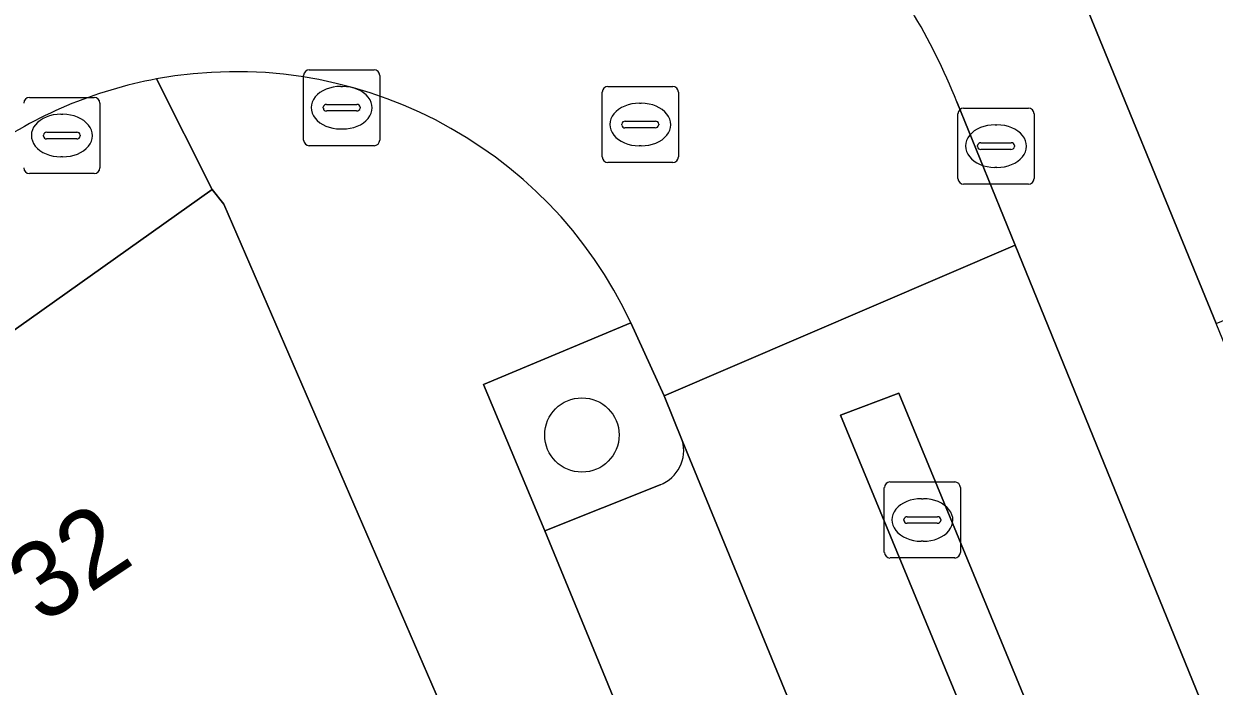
# Model space of a CAD drawing. Extents: x 161771 to 163125, y 382475 to 383179.
# Drawn here: x 161911.65 to 161927.3, y 383066.21 to 383074.92 of the extents above; entities that cross this region are included whole.
import ezdxf

# ---------------------------------------------------------------- set-up
doc = ezdxf.new("R2010")
doc.units = 0
for name, color, linetype in [('IMGEO_Boom', 7, 'Continuous'), ('IMGEO_Groenvoorziening', 7, 'Continuous'), ('IMGEO_Kolk', 7, 'Continuous'), ('IMGEO_Pand', 7, 'Continuous'), ('IMGEO_Pand_nummerreeks', 7, 'Continuous'), ('IMGEO_Parkeervlak_open', 7, 'Continuous'), ('IMGEO_Rijbaan_lokaal_open', 7, 'Continuous'), ('IMGEO_Rioolput', 7, 'Continuous'), ('IMGEO_Voetpad_open', 7, 'Continuous')]:
    doc.layers.add(name, color=color, linetype=linetype)

msp = doc.modelspace()

# ---------------------------------------------------------------- linework, layer by layer
at = {"layer": 'IMGEO_Boom'}
msp.add_circle((161918.987, 383069.512), 0.489, dxfattribs=at)
at = {"layer": 'IMGEO_Groenvoorziening'}
for points in [[(161920.07, 383070.029), (161919.632, 383070.986), (161917.694, 383070.178), (161918.501, 383068.252), (161920.014, 383068.858)], [(161920.306, 383069.44), (161920.07, 383070.029)]]:
    msp.add_lwpolyline(points, dxfattribs=at)
msp.add_arc((161919.843, 383069.308), 0.482, 290.8495, 15.8629, dxfattribs=at)
at = {"layer": 'IMGEO_Kolk'}
for p, q in [((161915.328, 383073.391), (161915.328, 383074.243)), ((161915.403, 383074.317), (161916.255, 383074.317)), ((161916.329, 383074.243), (161916.329, 383073.391)), ((161915.816, 383074.097), (161915.841, 383074.097)), ((161911.724, 383073.951), (161912.576, 383073.951)), ((161912.137, 383073.731), (161912.162, 383073.731)), ((161912.65, 383073.877), (161912.65, 383073.025)), ((161915.587, 383073.811), (161915.587, 383073.823)), ((161916.025, 383073.774), (161915.627, 383073.774)), ((161915.63, 383073.86), (161916.028, 383073.86)), ((161916.071, 383073.823), (161916.071, 383073.811)), ((161923.93, 383072.886), (161923.93, 383073.738)), ((161924.005, 383073.812), (161924.857, 383073.812)), ((161924.931, 383073.738), (161924.931, 383072.886)), ((161924.418, 383073.592), (161924.443, 383073.592)), ((161911.908, 383073.445), (161911.908, 383073.457)), ((161911.951, 383073.494), (161912.349, 383073.494)), ((161912.392, 383073.457), (161912.392, 383073.445)), ((161915.839, 383073.537), (161915.814, 383073.537)), ((161912.346, 383073.408), (161911.948, 383073.408)), ((161916.255, 383073.317), (161915.403, 383073.317)), ((161924.189, 383073.306), (161924.189, 383073.318)), ((161924.627, 383073.269), (161924.229, 383073.269)), ((161924.232, 383073.355), (161924.63, 383073.355)), ((161924.673, 383073.318), (161924.673, 383073.306)), ((161912.16, 383073.171), (161912.135, 383073.171)), ((161912.576, 383072.951), (161911.724, 383072.951)), ((161924.441, 383073.032), (161924.416, 383073.032)), ((161924.857, 383072.812), (161924.005, 383072.812)), ((161923.037, 383068.894), (161923.889, 383068.894)), ((161922.962, 383067.968), (161922.962, 383068.82)), ((161923.963, 383068.82), (161923.963, 383067.968)), ((161923.45, 383068.674), (161923.475, 383068.674)), ((161923.264, 383068.437), (161923.662, 383068.437)), ((161923.221, 383068.388), (161923.221, 383068.4)), ((161923.659, 383068.351), (161923.261, 383068.351)), ((161923.705, 383068.4), (161923.705, 383068.388)), ((161923.473, 383068.114), (161923.448, 383068.114)), ((161923.889, 383067.894), (161923.037, 383067.894))]:
    msp.add_line(p, q, dxfattribs=at)
for points in [[(161915.328, 383073.391), (161915.328, 383074.243)], [(161915.403, 383074.317), (161916.255, 383074.317)], [(161916.329, 383074.243), (161916.329, 383073.391)], [(161911.724, 383073.951), (161912.576, 383073.951)], [(161912.65, 383073.877), (161912.65, 383073.025)], [(161923.93, 383072.886), (161923.93, 383073.738)], [(161924.005, 383073.812), (161924.857, 383073.812)], [(161924.931, 383073.738), (161924.931, 383072.886)], [(161916.255, 383073.317), (161915.403, 383073.317)], [(161912.576, 383072.951), (161911.724, 383072.951)], [(161924.857, 383072.812), (161924.005, 383072.812)], [(161923.037, 383068.894), (161923.889, 383068.894)], [(161922.962, 383067.968), (161922.962, 383068.82)], [(161923.963, 383068.82), (161923.963, 383067.968)], [(161923.889, 383067.894), (161923.037, 383067.894)]]:
    msp.add_lwpolyline(points, dxfattribs=at)
for centre, radius, start, end in [((161915.405, 383074.241), 0.0765, 91.552, 178.448), ((161915.405, 383074.241), 0.0765, 91.552, 178.448), ((161916.253, 383074.241), 0.0765, 1.552, 88.448), ((161916.253, 383074.241), 0.0765, 1.552, 88.448), ((161911.726, 383073.875), 0.0765, 91.552, 178.448), ((161911.726, 383073.875), 0.0765, 91.552, 178.448), ((161912.574, 383073.875), 0.0765, 1.552, 88.448), ((161912.574, 383073.875), 0.0765, 1.552, 88.448), ((161915.627, 383073.82), 0.0403, 85.8775, 175.7526), ((161915.624, 383073.81), 0.0366, 178.938, 274.7102), ((161916.028, 383073.817), 0.043, 264.8664, 352.4533), ((161916.032, 383073.822), 0.0386, 1.7309, 96.639), ((161924.007, 383073.736), 0.0765, 91.552, 178.448), ((161924.007, 383073.736), 0.0765, 91.552, 178.448), ((161924.855, 383073.736), 0.0765, 1.552, 88.448), ((161924.855, 383073.736), 0.0765, 1.552, 88.448), ((161911.948, 383073.454), 0.0403, 85.8775, 175.7526), ((161911.945, 383073.444), 0.0366, 178.938, 274.7102), ((161912.349, 383073.451), 0.043, 264.8664, 352.4533), ((161912.353, 383073.456), 0.0386, 1.7309, 96.639), ((161915.405, 383073.393), 0.0765, 181.552, 268.448), ((161915.405, 383073.393), 0.0765, 181.552, 268.448), ((161916.253, 383073.393), 0.0765, 271.552, 358.448), ((161916.253, 383073.393), 0.0765, 271.552, 358.448), ((161924.229, 383073.315), 0.0403, 85.8775, 175.7526), ((161924.226, 383073.305), 0.0366, 178.938, 274.7102), ((161924.63, 383073.312), 0.043, 264.8664, 352.4533), ((161924.634, 383073.317), 0.0386, 1.7309, 96.639), ((161911.726, 383073.027), 0.0765, 181.552, 268.448), ((161911.726, 383073.027), 0.0765, 181.552, 268.448), ((161912.574, 383073.027), 0.0765, 271.552, 358.448), ((161912.574, 383073.027), 0.0765, 271.552, 358.448), ((161924.007, 383072.888), 0.0765, 181.552, 268.448), ((161924.007, 383072.888), 0.0765, 181.552, 268.448), ((161924.855, 383072.888), 0.0765, 271.552, 358.448), ((161924.855, 383072.888), 0.0765, 271.552, 358.448), ((161923.039, 383068.818), 0.0765, 91.552, 178.448), ((161923.039, 383068.818), 0.0765, 91.552, 178.448), ((161923.887, 383068.818), 0.0765, 1.552, 88.448), ((161923.887, 383068.818), 0.0765, 1.552, 88.448), ((161923.261, 383068.397), 0.0403, 85.8775, 175.7526), ((161923.666, 383068.399), 0.0386, 1.7309, 96.639), ((161923.258, 383068.387), 0.0366, 178.938, 274.7102), ((161923.662, 383068.394), 0.043, 264.8664, 352.4533), ((161923.039, 383067.97), 0.0765, 181.552, 268.448), ((161923.039, 383067.97), 0.0765, 181.552, 268.448), ((161923.887, 383067.97), 0.0765, 271.552, 358.448), ((161923.887, 383067.97), 0.0765, 271.552, 358.448)]:
    msp.add_arc(centre, radius, start, end, dxfattribs=at)
for centre, major_axis, ratio, start_param, end_param in [((161915.815, 383073.817), (-0.387, 0.002), 0.722429, 4.712389, 7.853982), ((161915.84, 383073.817), (-0.39, 0.002), 0.717154, 1.570796, 4.712389), ((161912.136, 383073.451), (-0.387, 0.002), 0.722429, 4.712389, 7.853982), ((161912.161, 383073.451), (-0.39, 0.002), 0.717154, 1.570796, 4.712389), ((161924.417, 383073.312), (-0.387, 0.002), 0.722429, 4.712389, 7.853982), ((161924.442, 383073.312), (-0.39, 0.002), 0.717154, 1.570796, 4.712389), ((161923.449, 383068.394), (-0.387, 0.002), 0.722429, 4.712389, 7.853982), ((161923.474, 383068.394), (-0.39, 0.002), 0.717154, 1.570796, 4.712389)]:
    msp.add_ellipse(centre, major_axis=major_axis, ratio=ratio, start_param=start_param, end_param=end_param, dxfattribs=at)
at = {"layer": 'IMGEO_Pand'}
for points in [[(161933.169, 383078.894), (161925.391, 383075.699), (161927.323, 383070.98), (161935.106, 383074.175)], [(161914.277, 383072.549), (161914.126, 383072.74), (161906.797, 383067.535), (161906.941, 383067.33), (161907.385, 383067.642), (161909.957, 383064.021), (161910.308, 383063.526), (161911.21, 383062.256), (161912.106, 383060.994), (161911.712, 383060.688), (161911.871, 383060.509), (161912.616, 383061.032), (161916.5, 383063.742), (161917.108, 383062.872), (161918.153, 383063.602)]]:
    msp.add_lwpolyline(points, close=True, dxfattribs=at)
at = {"layer": 'IMGEO_Parkeervlak_open'}
for points in [[(161927.275, 383052.464), (161920.306, 383069.44)], [(161920.014, 383068.858), (161918.501, 383068.252), (161925.161, 383052.062), (161926.698, 383052.703)]]:
    msp.add_lwpolyline(points, dxfattribs=at)
msp.add_arc((161919.843, 383069.308), 0.482, 290.8495, 15.8629, dxfattribs=at)
at = {"layer": 'IMGEO_Rijbaan_lokaal_open'}
msp.add_lwpolyline([(161919.632, 383070.986), (161920.07, 383070.029), (161924.683, 383072.01), (161923.916, 383073.896)], dxfattribs=at)
for points in [[(161922.387, 383069.775), (161923.152, 383070.063), (161929.185, 383055.447), (161935.336, 383040.651), (161941.307, 383026.98), (161943.177, 383027.812), (161941.403, 383031.963), (161932.608, 383052.538), (161924.683, 383072.01), (161920.07, 383070.029), (161920.306, 383069.44), (161927.275, 383052.464), (161927.918, 383050.884), (161932.616, 383039.884), (161933.342, 383038.281), (161938.378, 383026.395), (161938.63, 383025.789), (161940.535, 383026.637), (161934.585, 383040.452), (161928.401, 383055.201)], [(161922.387, 383069.775), (161928.401, 383055.201), (161934.585, 383040.452), (161940.535, 383026.637), (161941.307, 383026.98), (161935.336, 383040.651), (161929.185, 383055.447), (161923.152, 383070.063)]]:
    msp.add_lwpolyline(points, close=True, dxfattribs=at)
for centre, radius, start, end in [((161916.423, 383070.915), 8.064, 21.6977, 31.2414), ((161914.438, 383068.558), 5.733, 25.0504, 100.49), ((161914.44, 383068.563), 5.729, 100.5157, 125.2626)]:
    msp.add_arc(centre, radius, start, end, dxfattribs=at)
at = {"layer": 'IMGEO_Rioolput'}
for p, q in [((161919.329, 383074.096), (161920.181, 383074.096)), ((161919.254, 383073.17), (161919.254, 383074.022)), ((161920.255, 383074.022), (161920.255, 383073.17)), ((161919.742, 383073.876), (161919.767, 383073.876)), ((161919.513, 383073.59), (161919.513, 383073.602)), ((161919.556, 383073.639), (161919.954, 383073.639)), ((161919.997, 383073.602), (161919.997, 383073.59)), ((161919.951, 383073.553), (161919.553, 383073.553)), ((161919.765, 383073.316), (161919.74, 383073.316)), ((161920.181, 383073.096), (161919.329, 383073.096))]:
    msp.add_line(p, q, dxfattribs=at)
for points in [[(161919.329, 383074.096), (161920.181, 383074.096)], [(161919.254, 383073.17), (161919.254, 383074.022)], [(161920.255, 383074.022), (161920.255, 383073.17)], [(161920.181, 383073.096), (161919.329, 383073.096)]]:
    msp.add_lwpolyline(points, dxfattribs=at)
for centre, radius, start, end in [((161919.331, 383074.02), 0.0765, 91.552, 178.448), ((161919.331, 383074.02), 0.0765, 91.552, 178.448), ((161920.179, 383074.02), 0.0765, 1.552, 88.448), ((161920.179, 383074.02), 0.0765, 1.552, 88.448), ((161919.553, 383073.599), 0.0403, 85.8775, 175.7526), ((161919.55, 383073.589), 0.0366, 178.938, 274.7102), ((161919.954, 383073.596), 0.043, 264.8664, 352.4533), ((161919.958, 383073.601), 0.0386, 1.7309, 96.639), ((161919.331, 383073.172), 0.0765, 181.552, 268.448), ((161919.331, 383073.172), 0.0765, 181.552, 268.448), ((161920.179, 383073.172), 0.0765, 271.552, 358.448), ((161920.179, 383073.172), 0.0765, 271.552, 358.448)]:
    msp.add_arc(centre, radius, start, end, dxfattribs=at)
for centre, major_axis, ratio, start_param, end_param in [((161919.741, 383073.596), (-0.387, 0.002), 0.722429, 4.712389, 7.853982), ((161919.766, 383073.596), (-0.39, 0.002), 0.717154, 1.570796, 4.712389)]:
    msp.add_ellipse(centre, major_axis=major_axis, ratio=ratio, start_param=start_param, end_param=end_param, dxfattribs=at)
at = {"layer": 'IMGEO_Voetpad_open'}
for points in [[(161937.106, 383046.256), (161935.096, 383051.999), (161933.123, 383056.817), (161931.19, 383061.538), (161929.257, 383066.259), (161928.201, 383068.836), (161927.323, 383070.98), (161925.391, 383075.699), (161923.772, 383079.653), (161923.609, 383080.051), (161931.781, 383084.445), (161935.08, 383086.219), (161934.514, 383087.578), (161921.125, 383082.237), (161920.993, 383081.965), (161920.8, 383081.567), (161915.94, 383083.805), (161915.977, 383083.898), (161915.512, 383084.786), (161913.038, 383083.936), (161913.481, 383082.923)], [(161872.532, 383043.743), (161878.005, 383047.523), (161882.338, 383050.515), (161886.762, 383053.571), (161891.2, 383056.636), (161892.249, 383057.37), (161906.241, 383066.856), (161906.941, 383067.33), (161906.797, 383067.535), (161914.126, 383072.74), (161913.394, 383074.196)], [(161913.394, 383074.196), (161914.126, 383072.74), (161914.277, 383072.549), (161918.153, 383063.602), (161918.783, 383062.147), (161922.059, 383054.584), (161921.944, 383054.534), (161921.637, 383054.403), (161931.107, 383032.001), (161931.196, 383032.039), (161934.303, 383024.653), (161937.41, 383017.268), (161938.978, 383013.584), (161939.77, 383011.722), (161940.256, 383010.581), (161940.453, 383010.118), (161942.283, 383005.799), (161945.407, 382998.406), (161948.531, 382991.013)], [(161923.916, 383073.896), (161924.683, 383072.01), (161932.608, 383052.538), (161941.403, 383031.963), (161942.996, 383032.682), (161937.106, 383046.256)], [(161949.428, 382998.734), (161948.95, 383000), (161948.711, 383000.633), (161948.26, 383001.581), (161947.885, 383002.626), (161946.34, 383006.744), (161944.007, 383012.809), (161943.332, 383014.713), (161942.983, 383015.58), (161941.449, 383019.179), (161939.541, 383018.297), (161937.054, 383024.052), (161936.27, 383026.002), (161931.546, 383037.041), (161930.708, 383039.055), (161932.616, 383039.884), (161927.918, 383050.884), (161925.988, 383050.092), (161925.161, 383052.062), (161918.501, 383068.252), (161917.694, 383070.178), (161919.632, 383070.986)]]:
    msp.add_lwpolyline(points, dxfattribs=at)
for centre, radius, start, end in [((161916.423, 383070.915), 8.064, 21.6977, 31.2414), ((161914.438, 383068.558), 5.733, 25.0504, 100.49), ((161914.44, 383068.563), 5.729, 100.5157, 125.2626)]:
    msp.add_arc(centre, radius, start, end, dxfattribs=at)

# ---------------------------------------------------------------- texts
at = {"layer": 'IMGEO_Pand_nummerreeks'}
msp.add_text('32', height=1, rotation=33.7759, dxfattribs=at).set_placement((161911.893, 383067.009))

doc.saveas('drawing.dxf')
